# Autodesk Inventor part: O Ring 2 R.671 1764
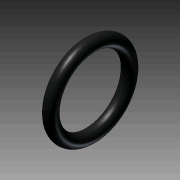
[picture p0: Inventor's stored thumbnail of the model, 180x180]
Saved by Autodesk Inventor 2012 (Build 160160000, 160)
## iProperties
Created: 2007-11
Part Number: O Ring 2 R.671 1764
Document SubType Name: Modeling
Designer: lwoods
Density: 1 g/cm^3
Material: Default
Author: lwoods
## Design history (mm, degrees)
sketch "Sketch1" dims "d0" = 3.175
  geometry: L1 (-23.425, -3.072)-(10.369, -3.072); L2 (-6.452, 7.037)-(-6.452, 5.45); L3 (-6.452, 5.45)-(-6.452, -3.072)
  constraints: 6 end point, 2 perpendicular, 1 horizontal, 1 point on line, 1 vertical alignment, 2 other
  dimensions: "d1" = 8.5217 distance of L3.end L2.end
revolve "Revolution1" sketch "Sketch1" stored, may be unused: angle "d2" = 90 deg
body "Solid1"
